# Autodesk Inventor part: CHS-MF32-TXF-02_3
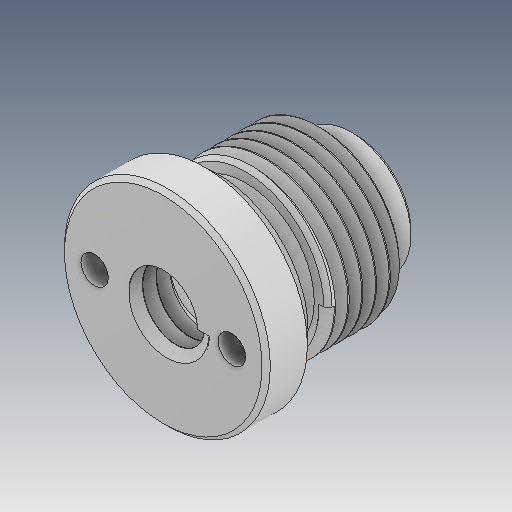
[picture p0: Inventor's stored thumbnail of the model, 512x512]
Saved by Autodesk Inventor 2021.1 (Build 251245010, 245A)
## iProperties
Created: 2021-05
Part Number: CHS-MF32-TXF-02_3
Material: Ogólny
Document SubType Name: Modeling
Designer: user
Density: 1 g/cm^3
Appearance: Domyślna
Author: user
Revision Number: ÈÎºÎ
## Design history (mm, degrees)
feature "ÊäÈë1"
node "Bryła1"
